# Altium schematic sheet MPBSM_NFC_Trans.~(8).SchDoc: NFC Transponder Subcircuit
size A3; Date: Not shown in title block; ApprovedBy: Not shown in title block; CheckedBy: Not shown in title block; Author: Not shown in title block; CompanyName: Not shown in title block; DrawnBy: Not shown in title block; Engineer: Not shown in title block; Organization: Not shown in title block; Address1: Not shown in title block; Address2: Not shown in title block; Address3: Not shown in title block; Address4: Not shown in title block; DocumentNumber: 7; Revision: Use project parameter SCH_Rev; SheetNumber: 9; SheetTotal: 12; PageSetup: Record=PageOptions¦CenterHorizontal=True¦CenterVertical=True¦PrintScale=0.69¦XCorrection=1.00¦YCorrection=1.00¦PrintKind=0¦BorderSize=5000000¦LeftOffset=0¦BottomOffset=0¦Orientation=2¦PaperLength=1000¦PaperWidth=1000¦Scale=100¦PaperSource=15¦PrintQuality=600¦MediaType=1¦DitherType=10¦PaperKind=Letter¦PrintScaleMode=1
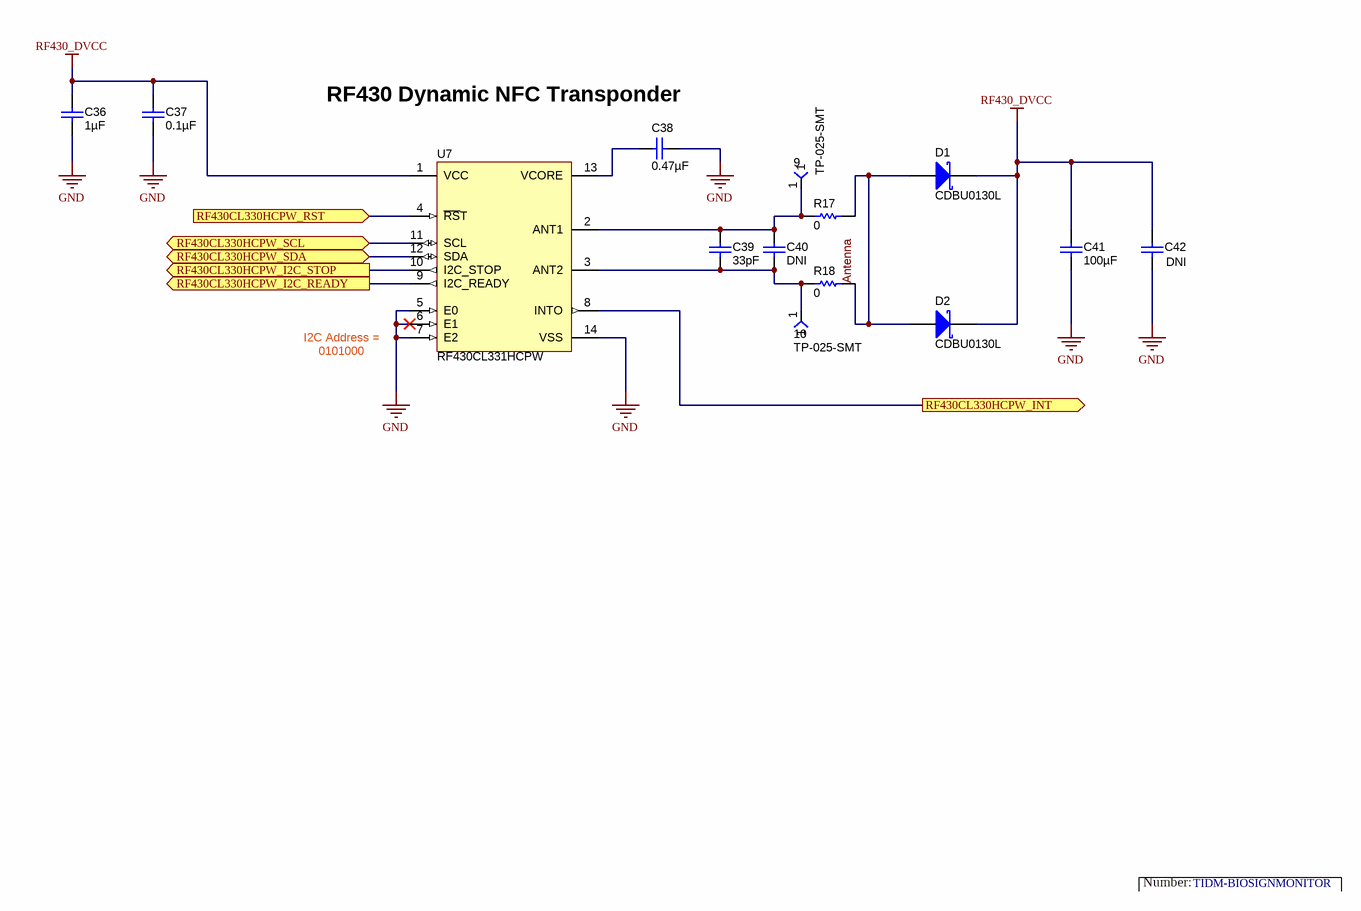
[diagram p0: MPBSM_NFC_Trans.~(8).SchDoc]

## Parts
9  TP-025-SMT  [TP_25MIL-SMT]
10  TP-025-SMT  [TP_25MIL-SMT]
C36  ValueDisplayed: 1µF  [0402]  (hidden comment: C1005X5R0J105M)
C37  ValueDisplayed: 0.1µF  [0402]  (hidden comment: C1005X5R1A104K)
C38  ValueDisplayed: 0.47µF  [0402]  (hidden comment: GRM155R60J474KE19D)
C39  ValueDisplayed: 33pF  [0603]  (hidden comment: C1608C0G1H330J)
C40  GRM1555C1H390JA01D  [0402]  (value not drawn)
C41  ValueDisplayed: 100µF  [1206_190]  (hidden comment: C3216X5R1A107M160AC)
C42  Used in BOM report  [0603]  (value not drawn)
D1  CDBU0130L  [SOD-523F]
D2  CDBU0130L  [SOD-523F]
R17  ValueDisplayed: 0  [0402]  (hidden comment: ERJ-2GE0R00X)
R18  ValueDisplayed: 0  [0402]  (hidden comment: ERJ-2GE0R00X)
U7  RF430CL331HCPW  [PW0014A_M]

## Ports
RF430CL330HCPW_I2C_READY (out), RF430CL330HCPW_I2C_STOP (out), RF430CL330HCPW_INT (out), RF430CL330HCPW_RST (in), RF430CL330HCPW_SCL (bidir), RF430CL330HCPW_SDA (bidir)

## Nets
GND: C36.2 C37.2 C38.1 C41.2 C42.2 U7.5(E0) U7.6(E1) U7.7(E2) U7.14(VSS)
RF430_DVCC: C36.1 C37.1 C41.1 C42.1 D1.1(K) D2.1(K) U7.1(VCC)
Antenna: D1.2(A) D2.2(A) R17.2 R18.2
RF430CL330HCPW_I2C_READY: U7.9(I2C_READY) ; port RF430CL330HCPW_I2C_READY
RF430CL330HCPW_I2C_STOP: U7.10(I2C_STOP) ; port RF430CL330HCPW_I2C_STOP
RF430CL330HCPW_INT: U7.8(INTO) ; port RF430CL330HCPW_INT
RF430CL330HCPW_RST: U7.4(~{RS}T) ; port RF430CL330HCPW_RST
RF430CL330HCPW_SCL: U7.11(SCL) ; port RF430CL330HCPW_SCL
RF430CL330HCPW_SDA: U7.12(SDA) ; port RF430CL330HCPW_SDA
Net9_1: 9.1 C39.1 C40.1 R17.1 U7.2(ANT1)
Net10_1: 10.1 C39.2 C40.2 R18.1 U7.3(ANT2)
NetC38_2: C38.2 U7.13(VCORE)

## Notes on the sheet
- (near C38) RF430 Dynamic NFC Transponder
- I2C Address =
- 0101000
- Number:
- TIDM-BIOSIGNMONITOR

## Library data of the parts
9 10 = TP-025-SMT: Test Point, O.025"; Manufacturer: STD; Value: STD
C36 = C1005X5R0J105M: CAP, CERM, 1 µF, 6.3 V, +/- 20%, X5R, 0402; Manufacturer: TDK; Polarized: N; CompType: Capacitor; Value: 1uF; U/M: EA; Cap_F: 0.000001; Tolerance_%: 20; ESR_ohm: 0.0079; Value1: 0.0079 ohm; VDC_V: 6.3; Value2: 6.3V; TaMin_C: -55; TaMax_C: 85
C37 = C1005X5R1A104K: CAP, CERM, 0.1 µF, 10 V, +/- 10%, X5R, 0402; Manufacturer: TDK; Polarized: N; CompType: Capacitor; Value: 0.1uF; U/M: EA; Cap_F: 0.0000001; Tolerance_%: 10; ESR_ohm: 0.0186; Value1: 0.0186 ohm; Value2: 10V; TaMin_C: -55; TaMax_C: 85
C38 = GRM155R60J474KE19D: CAP, CERM, 0.47 µF, 6.3 V, +/- 10%, X5R, 0402; Manufacturer: MuRata; Polarized: N; CompType: Capacitor; Value: 0.47uF; U/M: EA; Cap_F: 0.00000047; Tolerance_%: 10; Value1: Unknown; VDC_V: 6.3; Value2: 6.3V; TaMin_C: -55; TaMax_C: 85
C39 = C1608C0G1H330J: CAP, CERM, 33 pF, 50 V, +/- 5%, C0G/NP0, 0603; Manufacturer: TDK; Polarized: N; CompType: Capacitor; Value: 33pF; U/M: EA; Cap_F: 0.000000000033; Tolerance_%: 5; ESR_ohm: 0.2649; Value1: 0.2649 ohm; VDC_V: 50; Value2: 50V; TaMin_C: -55; TaMax_C: 125
C40 = GRM1555C1H390JA01D: CAP, CERM, 39pF, 50V, +/-5%, C0G/NP0, 0402; Manufacturer: MuRata; Polarized: N; CompType: Capacitor; U/M: EA; Cap_F: 0.000000000039; Tolerance_%: 5; Value1: Unknown; VDC_V: 50; TaMin_C: -55; TaMax_C: 125
C41 = C3216X5R1A107M160AC: CAP, CERM, 100 µF, 10 V, +/- 20%, X5R, 1206_190; Manufacturer: TDK; Polarized: N; CompType: Capacitor; Value: 100uF; U/M: EA; Cap_F: 0.0001; Tolerance_%: 20; Value1: Unknown; VDC_V: 10; Value2: 10V; TaMin_C: -55; TaMax_C: 85
C42 = Capacitor: CAP, CERM, xxxF, xxV, [TempCo], xx%, [PackageReference]; Polarized: N; Value: Not Applicable; U/M: EA
D1 D2 = CDBU0130L: Diode, Schottky, 35V, 0.1A, SOD-523F; Manufacturer: Comchip Technology; U/M: EA; Value2: V; Io_A: 0.1; Vr_V: 35; TJmax_C: 125
R17 R18 = ERJ-2GE0R00X: RES, 0, 5%, 0.063 W, 0402; Manufacturer: Panasonic; CompType: Resistor; Value: 0; Value_Code: 0000; Tolerance_%: 5; Power_W: 0.063; Value2: 0.063W; VDC_V: 50; TempCo: 600 ppm/C; EIA_Code: E24; U/M: EA
U7 = RF430CL331H: The Texas Instruments Dynamic NFC Interface Transponder RF430CL331H is an NFC Tag Type 4 device  that combines a wireless NFC interface and a wired SPI or I2C interface to connect the device to a host.; Alternate PartNumber: RF430CL330HCPW; SymbolCreator: a0272897; CompType: IC; U/M: EA, IN, or GM; SupplyVoltageMax_V: 3.6V; SupplyVoltageMin_V: 2 V; SupplyVoltage: 2 V - 3.6 V; SupplyCurrent: 250 uA; TaMax_C: 85 °C; TaMin_C: -40 °C; Value: Mixed-Signal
